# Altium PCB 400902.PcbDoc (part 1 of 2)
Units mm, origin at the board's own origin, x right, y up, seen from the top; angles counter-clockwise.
Board outline 45.72 x 50.8 mm, 4 copper layers (Top Layer, Mid-Layer 1, Mid-Layer 2, Bottom Layer), stack 1.564 mm thick; 61 components, 50 nets, 204 pads, 509 vias.
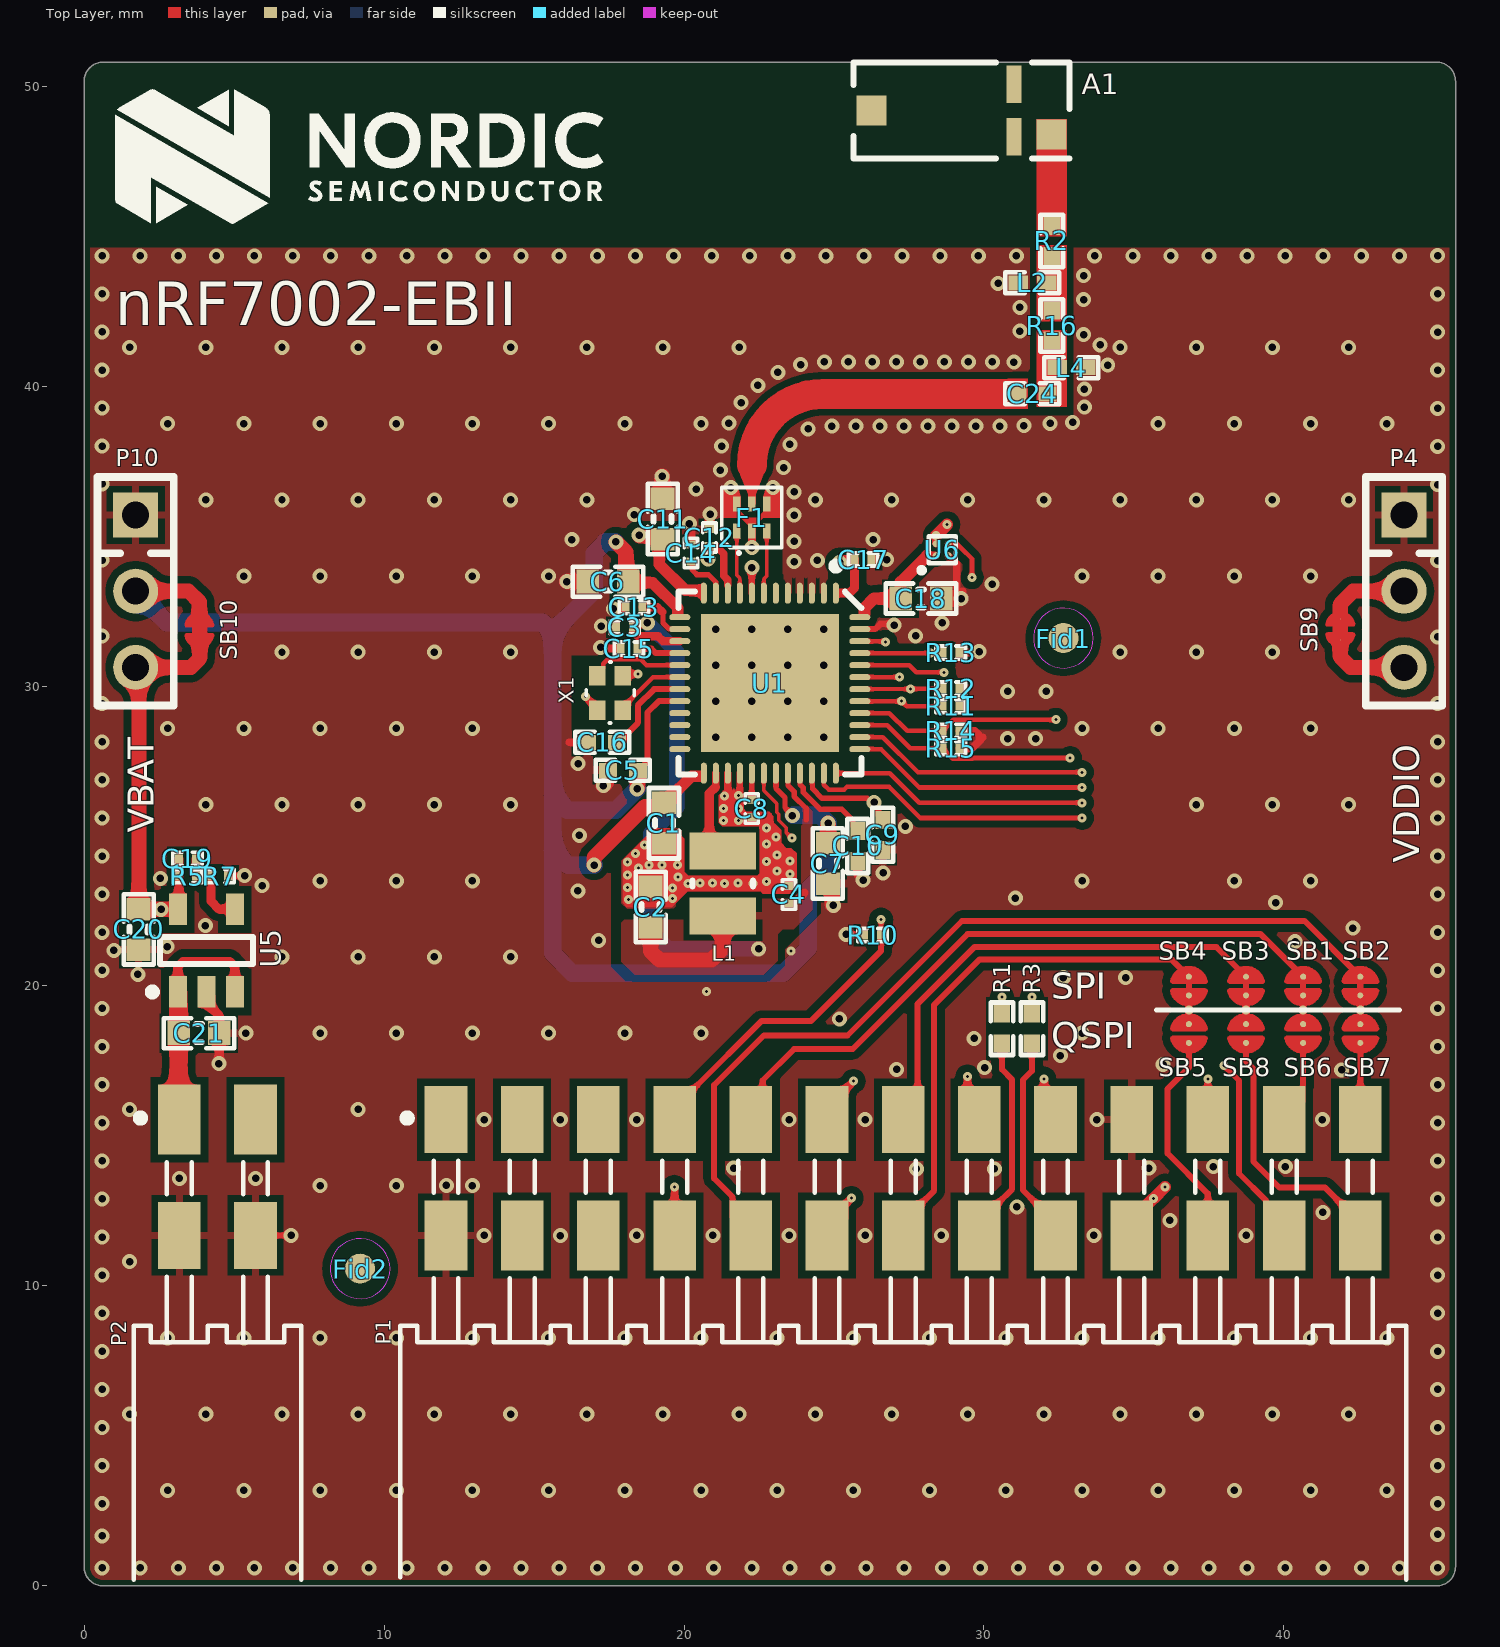
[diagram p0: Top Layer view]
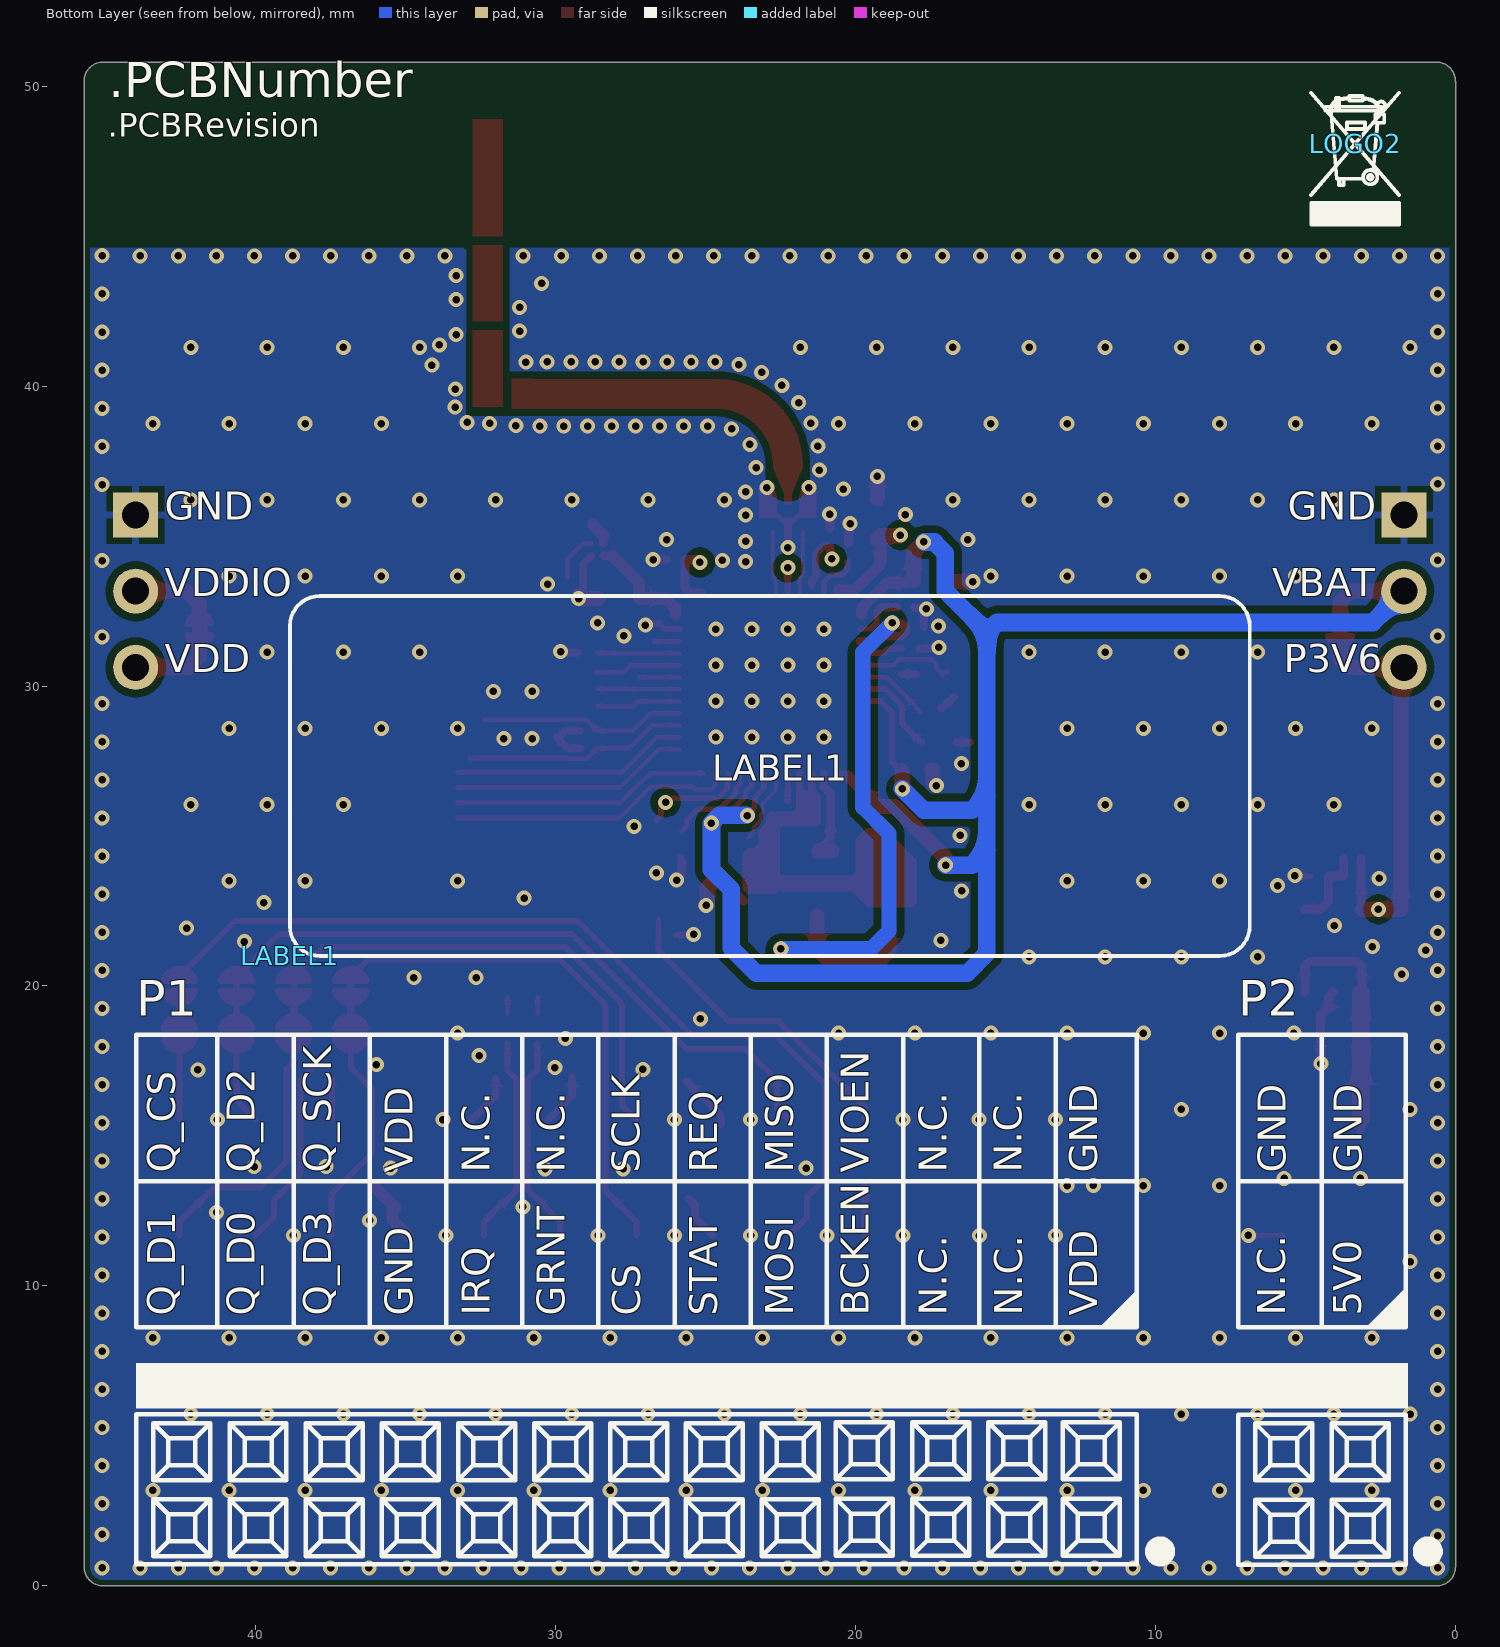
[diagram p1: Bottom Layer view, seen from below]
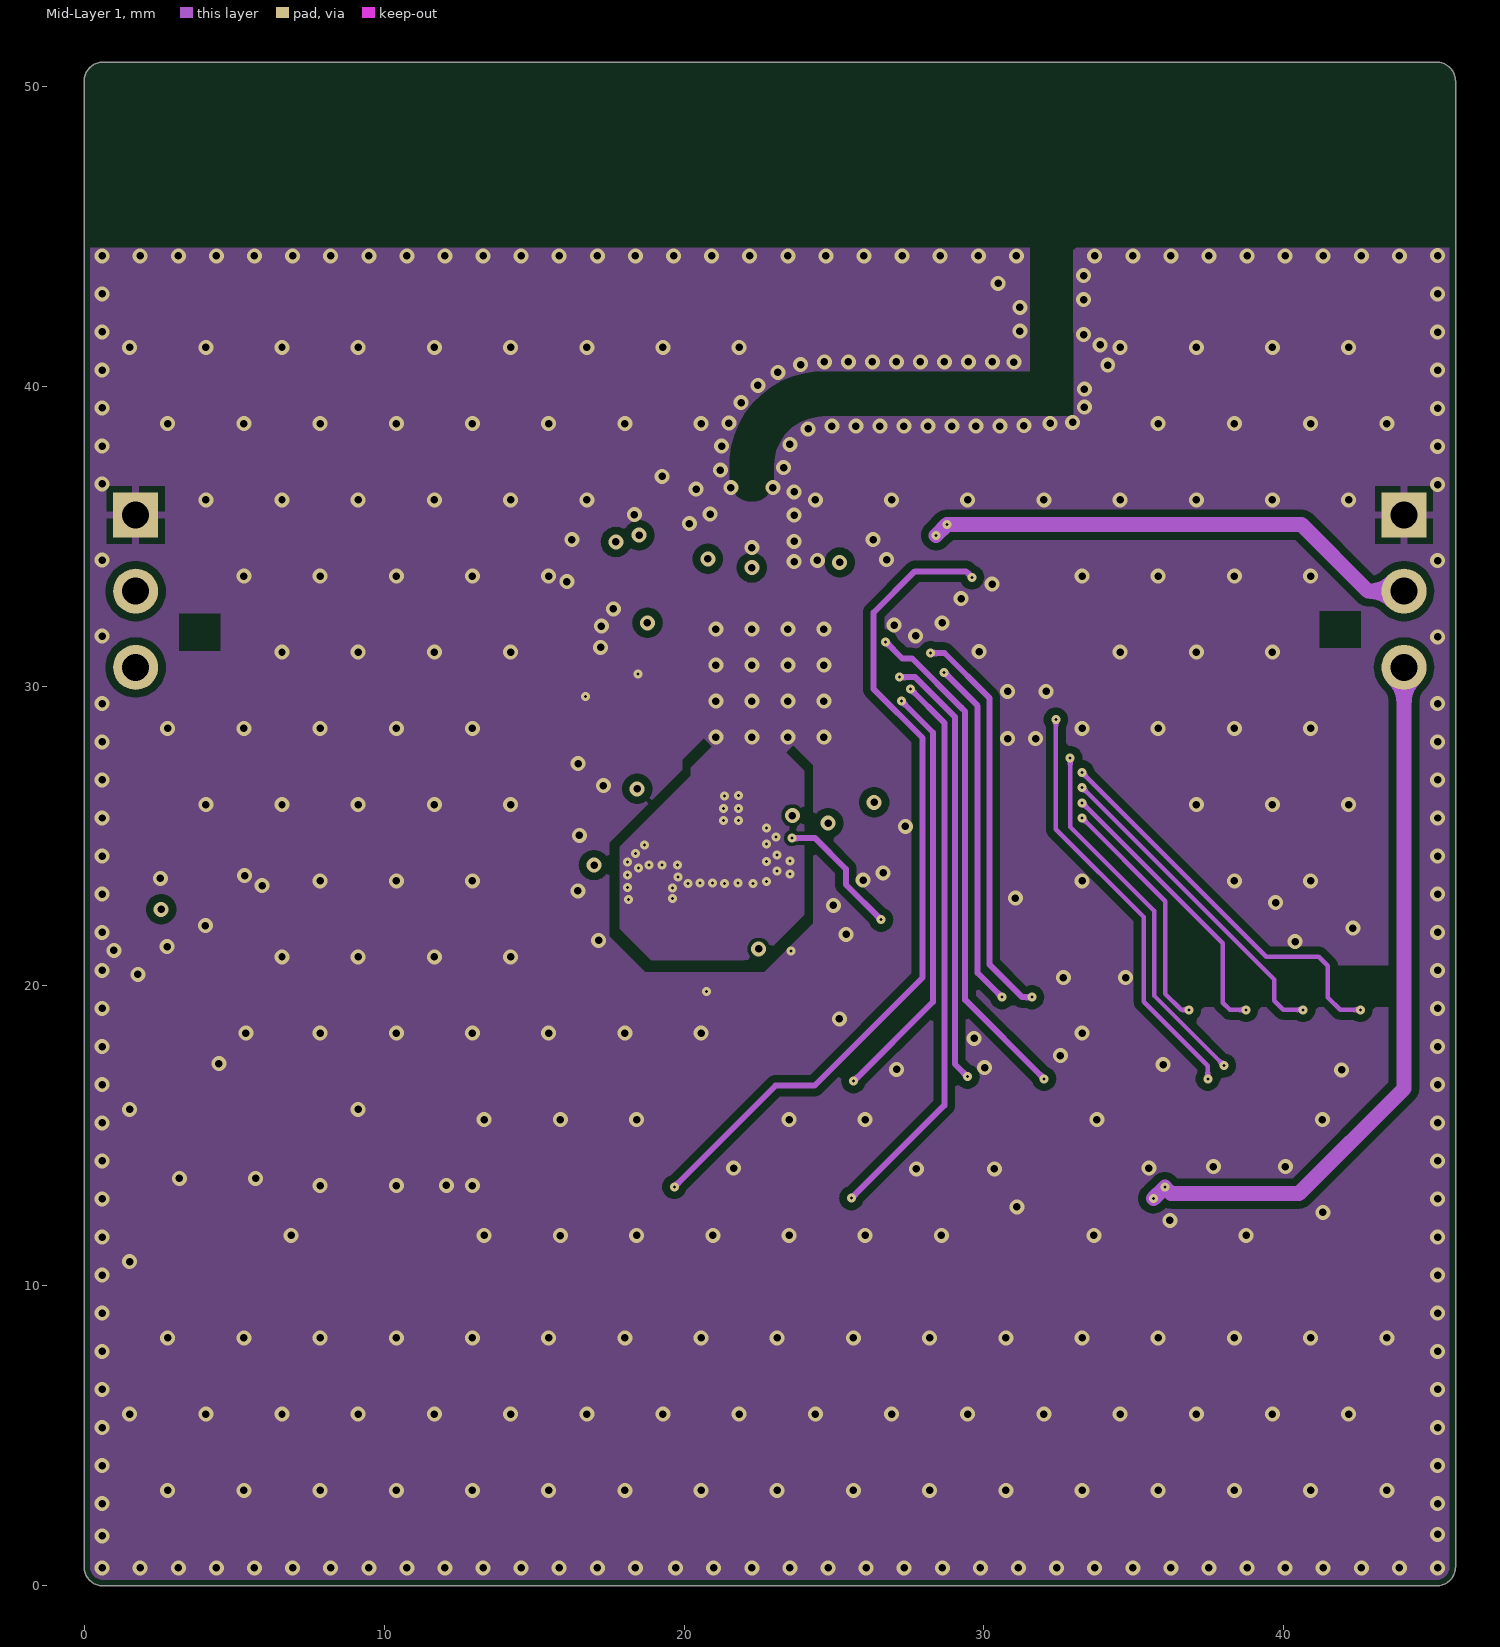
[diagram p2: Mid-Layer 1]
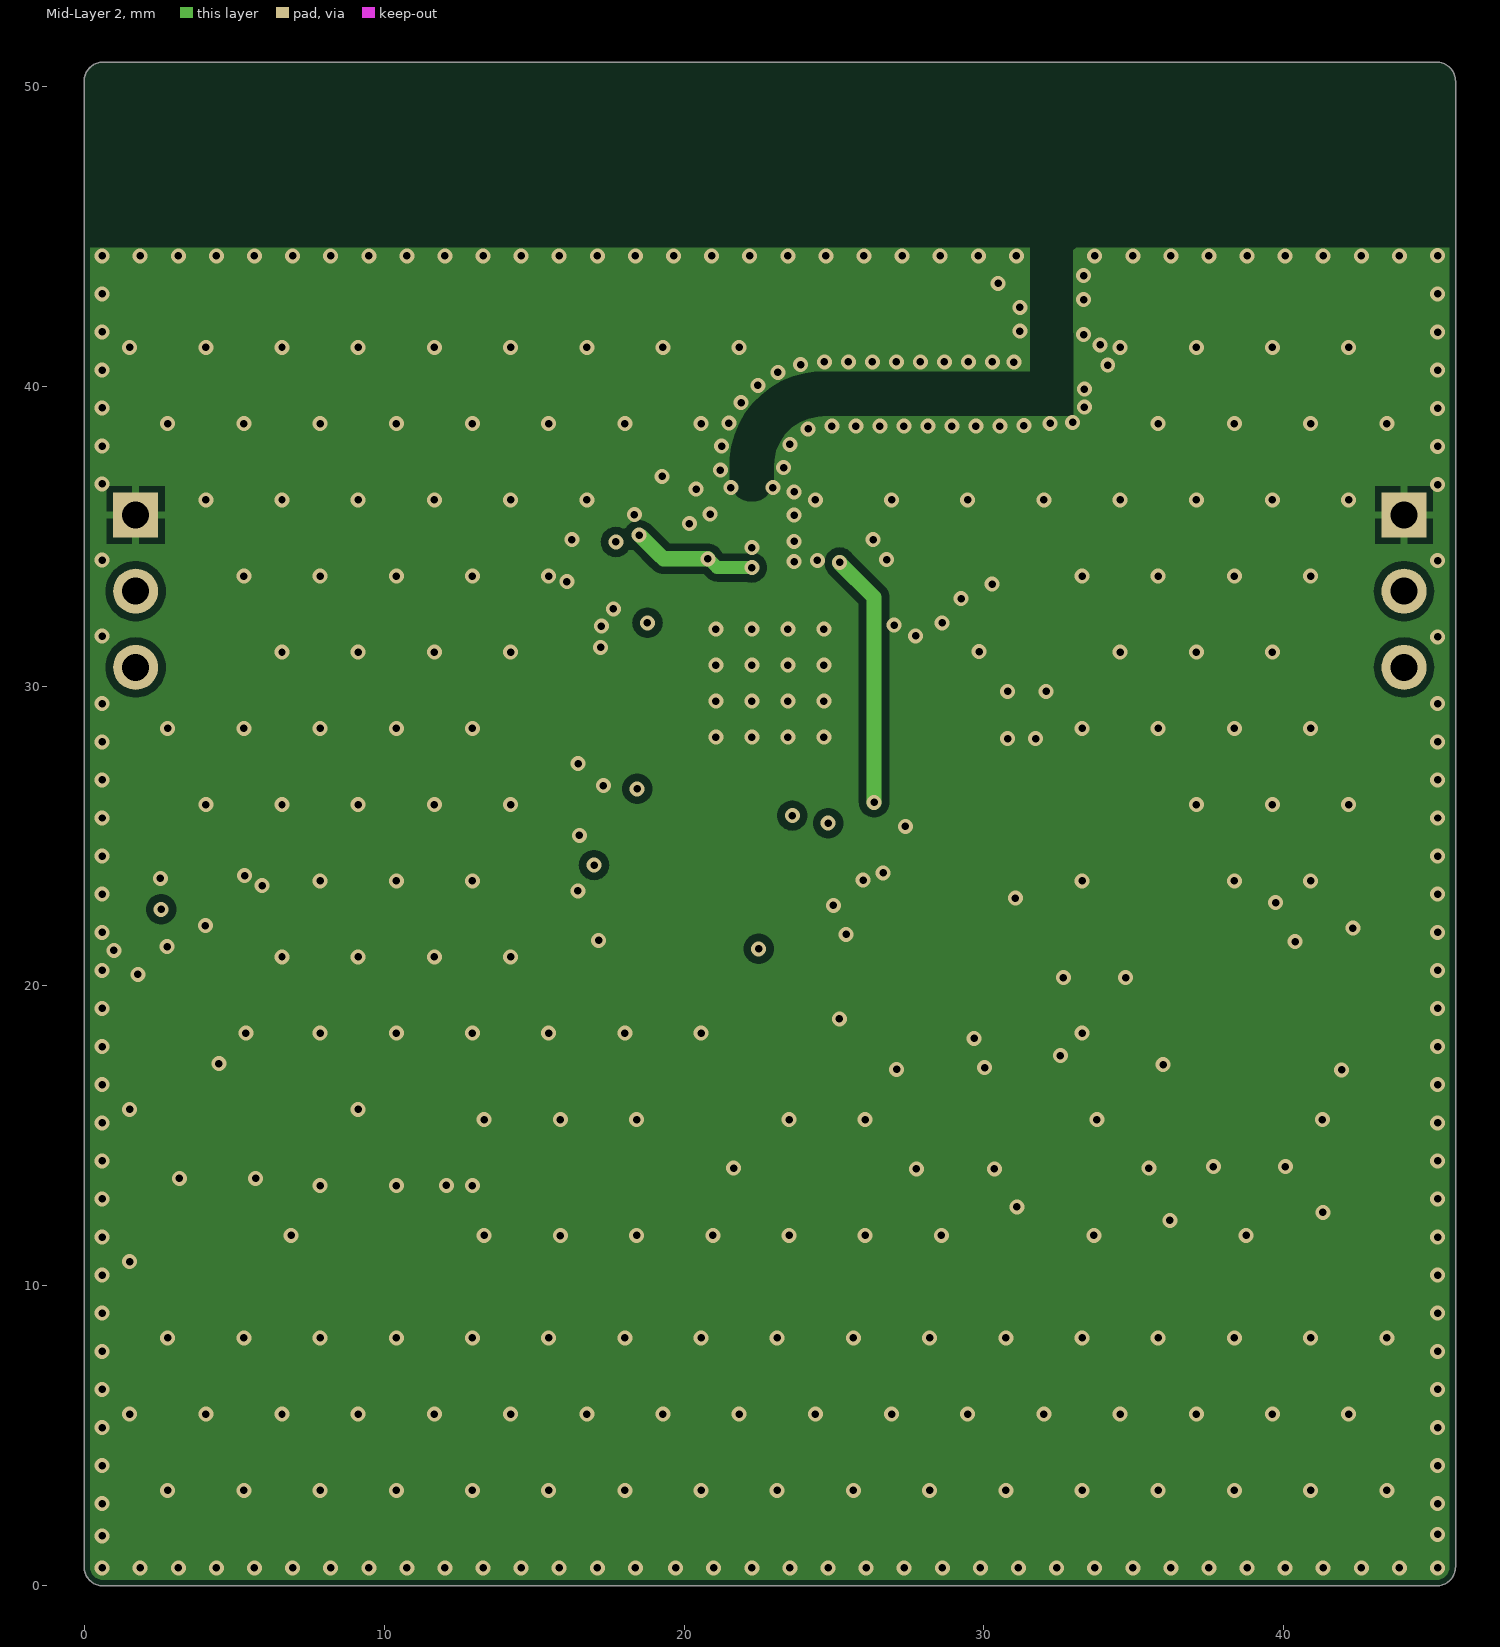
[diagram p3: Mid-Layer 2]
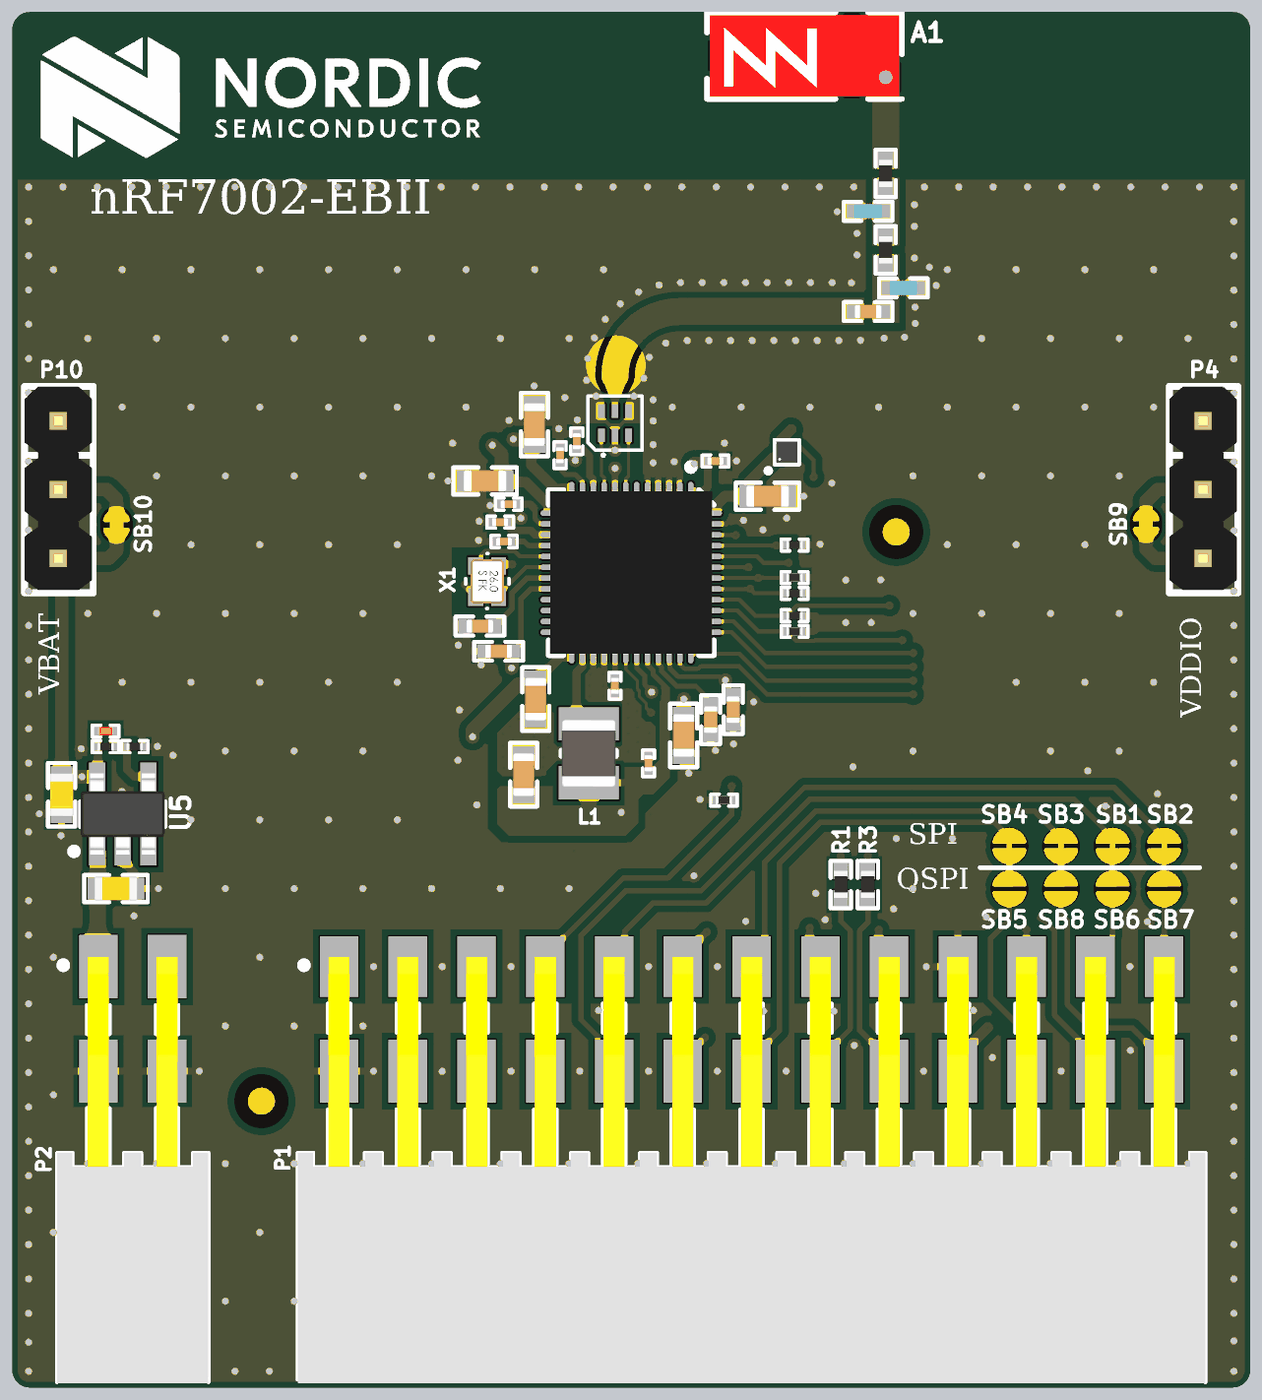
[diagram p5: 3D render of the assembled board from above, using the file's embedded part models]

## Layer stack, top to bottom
Top Solder: solder mask 0.0254, Solder Resist Blue, Dk 4
Top Layer: signal copper 0.0356
Dielectric1: prepreg 0.076, FR-4, Dk 4.4
Mid-Layer 1: signal copper 0.0356
Dielectric2: core 1.27, FR-4, Dk 4.4
Mid-Layer 2: signal copper 0.0356
Dielectric3: prepreg 0.076, FR-4, Dk 4.4
Bottom Layer: signal copper 0.0356
Bottom Solder: solder mask 0.0254, Solder Resist Blue, Dk 4

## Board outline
0,0.635 ccw(c0.635,0.635) 0.635,0 45.085,0 ccw(c45.085,0.635) 45.72,0.635 45.72,50.164 ccw(c45.085,50.164) 45.085,50.799 45.085,50.8 0.636,50.8 0.636,50.799 ccw(c0.636,50.164) 0.001,50.164 0,50.164

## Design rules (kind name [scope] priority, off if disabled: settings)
BoardOutlineClearance [Not (InComponent('A1') or InComponent('P1')or InComponent('P2') or HasPad('Free-666'))] p1: gap=0.2 ignorepadtopadclearanceinfootprint=FALSE
Clearance RF_Clerance [InNetClass('RF') vs InPoly] p1: gap=0.23 ignorepadtopadclearanceinfootprint=FALSE
Clearance Polygon_Clearance [(InNamedPolygon('Top_Layer-GND')) or (InNamedPolygon('Bottom_Layer-GND')) or (InNamedPolygon('Mid_Layer_1-GND')) or (InNamedPolygon('Mid_Layer_2-GND'))] p2: gap=0.25 ignorepadtopadclearanceinfootprint=FALSE
Clearance U1_Clearance [TouchesRoom('nRF7002_room') vs OnTopLayer] p3: gap=0.12 ignorepadtopadclearanceinfootprint=FALSE
Clearance [All] p4: gap=0.125 ignorepadtopadclearanceinfootprint=FALSE
DiffPairsRouting [All] p1: maxlimit=0.254 minlimit=0.15 mostfreqgap=0.254 toplayer_maxgap=0.15 toplayer_prefgap=0.15 toplayer_minwidth=0.203 toplayer_maxwidth=0.381 toplayer_prefwidth=0.381 midlayer1_mingap=0.254 midlayer1_minwidth=0.203 midlayer1_maxwidth=0.381 midlayer1_prefwidth=0.381 midlayer2_mingap=0.254 midlayer2_minwidth=0.203 midlayer2_maxwidth=0.381 midlayer2_prefwidth=0.381 bottomlayer_maxgap=0.15 bottomlayer_prefgap=0.15 bottomlayer_minwidth=0.203 bottomlayer_maxwidth=0.381 bottomlayer_prefwidth=0.381 maxuncoupledlength=12.7
FabricationTestPointUsage TestPointUsage [All] p1: valid=0 allowmultiple=FALSE
FabricationTestpoint Testpoint [All] p1: side=3 testpointundercomponent=TRUE minsize=1.016 maxsize=2.54 preferedsize=1.524 minholesize=0 maxholesize=1.016 preferedholesize=0.813 testpointgrid=0.025 allowsidetop=TRUE allowsidebottom=TRUE usegrid=TRUE gridtolerance=0
Height [All] p1 off: minheight=0 maxheight=25.4 prefheight=12.7
HoleSize [All] p1: absolutevalues=TRUE maxlimit=5 minlimit=0.1 maxpercent=80.000 minpercent=20.000
HoleToHoleClearance [All] p1: gap=0.25 allowstackedmicrovias=FALSE
MinimumAnnularRing [All] p1: minimumring=0.1
MinimumSolderMaskSliver [Not InComponent('U1')] p1: minsoldermaskwidth=0.075
PolygonConnect PolygonConnect_Via [isVia and innet(gnd)] p1: connectstyle=Direct reliefconductorwidth=0.254 reliefentries=4 polygonreliefangle="90 Angle" airgapwidth=0.254
PolygonConnect PolygonConnect_footprint [HasFootprint('INDC1005X04L_C2') or  HasFootprint('CAPC1005X04L_C2') or  HasFootprint('RESC1005X04L_C2') or   HasFootprint('CAPC1608X06L') or  HasFootprint('CAPC2012X11L') or  HasFootprint('SOT95P280X140-5N')] p2: connectstyle=Direct reliefconductorwidth=0.254 reliefentries=4 polygonreliefangle="90 Angle" airgapwidth=0.254
PolygonConnect [All] p3: connectstyle=Relief reliefconductorwidth=0.254 reliefentries=4 polygonreliefangle="90 Angle" airgapwidth=0.213
RoomDefinition nRF7002_room [False vs False] p1: confinementstyle=ConfineIn formatcopy=TRUE lockcomponents=FALSE outline 15.374,37.727 29.243,37.727 29.243,25.1 15.374,25.1
RoutingVias [All] p1: holewidth=0.25 width=0.5 viastyle="Through Hole" minholewidth=0.1 minwidth=0.5 maxholewidth=0.711 maxwidth=1.27
SilkToSolderMaskClearance SilkscreenOverComponentPads [IsPad vs Not (HasFootprint('CAPC1608X06L') or HasFootprint('CAPC0603X03L_C') or HasFootprint('CAPC1005X04L') or HasFootprint('INDC1005X04L') or HasFootprint('RESC0603X03L_C') or HasFootprint('LED_0603_G') or HasFootprint('BGA4C40P2X2_76X76X62') or  HasFootprint('RESC1005X04L') or HasFootprint('INDC1005X04L_WW'))] p1: minsilkscreentomaskgap=0.1 clearancetoexposedcopper=TRUE
SolderMaskExpansion SolderMaskExpansion_via [IsVia] p1: expansion=0.076 istentingtop=TRUE
SolderMaskExpansion SolderMaskExpansion_1 [All] p2: expansion=0.076 istentingtop=FALSE
Width U1_Width [All] p1: maxlimit=2.54 minlimit=0.11 preferedwidth=0.15
Width [All] p2: maxlimit=2.54 minlimit=0.15 preferedwidth=0.15
22 further rules are at their usual default settings.

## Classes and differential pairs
net class RF: ANT ANTWIFI NetC24_1 NetL2_2 TXRF0 TXRF1

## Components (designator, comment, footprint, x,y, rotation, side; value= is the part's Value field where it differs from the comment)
A1 "NN03-320" NN03-320 29.257,49.19 r0 top locked
C1 "4.7µF" CAPC1608X06L 19.332,25.426 r90 top
C2 "4.7µF" CAPC1608X06L 18.887,22.632 r270 top
C3 "0.22µF" CAPC0603X03L_C 18.018,31.959 r0 top
C4 "0.47µF" CAPC0603X03L_C 23.499,23.052 r270 top
C5 "1.0µF" CAPC1005X04L 17.962,27.191 r0 top
C6 "4.7µF" CAPC1608X06L 17.461,33.481 r0 top
C7 "2.2µF" CAPC1608X06L 24.796,24.083 r270 top
C8 "10nF" CAPC0603X03L_C 22.258,25.916 r270 top
C9 "2.2µF" CAPC1005X04L 26.63,25.037 r90 top
C10 "1.0µF" CAPC1005X04L 25.794,24.667 r270 top
C11 "4.7µF" CAPC1608X06L 19.285,35.563 r270 top
C12 "100nF" CAPC0603X03L_C 20.848,34.947 r90 top
C13 "22nF" CAPC0603X03L_C 18.331,32.626 r0 top
C14 "0.47µF" CAPC0603X03L_C 20.232,34.432 r270 top
C15 "2.2µF" CAPC0603X03L_C 18.162,31.245 r0 top
C16 "1.0µF" CAPC1005X04L 17.27,28.121 r0 top
C17 "100nF" CAPC0603X03L_C 25.971,34.217 r180 top
C18 "2.2µF" CAPC1608X06L 27.898,32.917 r180 top
C19 "82pF" CAPC0603X03L_C 3.443,24.24 r0 top locked
C20 "4.7µF" CAPC1608X06L 1.818,21.89 r90 top locked
C21 "4.7µF" CAPC1608X06L 3.825,18.425 r180 top locked
C24 "0.7pF" CAPC1005X04L 31.61,39.738 r180 top
F1 "LFD_Diplexer" CAF-50P160X80-6N 22.26,35.615 r90 top value=LFD182G45DCJD247
Fid1 "Fiducial mark" Fiducial 32.647,31.597 r0 top value=N.A.
Fid2 "Fiducial mark" Fiducial 9.2,10.575 r0 top value=N.A.
L1 "3.3µH" INDC2520X10N 21.289,23.421 r270 top
L2 "7.0nH" INDC1005X04L_WW 31.61,43.441 r0 top locked
L4 "2.4nH" INDC1005X04L_WW 32.91,40.612 r180 top
LABEL1 "12x32mm" LabelSilk_12x32 38.86,21 r180 bottom
LOGO2 "WEE Symbol" WEEE_3x4.5mm 3.35,48.075 r180 bottom
P1 "Socket 2x13, Angled" SOCKET_ANG_2x13_SMD-2.54mm-Mirrored 27.305,13.614 r0 top locked
P2 "Socket 2x2, Angled" SOCKET_ANG_2x2_SMD-2.54mm-Mirrored 4.445,13.614 r0 top locked
P4 "Pin List 1x3" LIST_1x3 44.003,33.16 r270 top
P10 "Pin List 1x3" LIST_1x3 1.718,33.16 r270 top
R1 "0R" RESC1005X04L 30.6,18.575 r90 top
R2 "0R" RESC1005X04L 32.26,44.84 r270 top locked
R3 "0R" RESC1005X04L 31.6,18.575 r90 top
R5 "560k" RESC0603X03L_C 3.443,23.665 r180 top locked
R7 "160k" RESC0603X03L_C 4.518,23.665 r180 top locked
R10 "100k" RESC0603X03L_C 26.286,21.694 r180 top
R11 "100k" RESC0603X03L_C 28.894,29.332 r0 top
R12 "100k" RESC0603X03L_C 28.894,29.91 r0 top
R13 "100k" RESC0603X03L_C 28.894,31.114 r180 top
R14 "100k" RESC0603X03L_C 28.894,28.503 r0 top
R15 "100k" RESC0603X03L_C 28.894,27.925 r0 top
R16 "0R" RESC1005X04L 32.26,42.015 r270 top locked
SB1 "Solderbridge" Solderbridge_SHORTED_0.4 40.64,19.997 r90 top locked net-tie
SB2 "Solderbridge" Solderbridge_SHORTED_0.4 42.545,19.997 r90 top locked net-tie
SB3 "Solderbridge" Solderbridge_SHORTED_0.4 38.735,19.997 r90 top locked net-tie
SB4 "Solderbridge" Solderbridge_SHORTED_0.4 36.83,19.997 r90 top locked net-tie
SB5 "Solderbridge" Solderbridge_0.4#1 36.83,18.415 r270 top locked
SB6 "Solderbridge" Solderbridge_0.4#1 40.64,18.415 r270 top locked
SB7 "Solderbridge" Solderbridge_0.4#1 42.545,18.415 r270 top locked
SB8 "Solderbridge" Solderbridge_0.4#2 38.735,18.415 r270 top locked
SB9 "Solderbridge" Solderbridge_Shorted_Power 41.872,31.883 r270 top net-tie
SB10 "Solderbridge" Solderbridge_Shorted_Power 3.85,31.86 r90 top net-tie
U1 "nRF7002-QFAA" QFN40P600X600X60-48N 22.86,30.095 r270 top
U5 "AP2127" SOT95P282X145-5N 4.075,21.175 r90 top locked
U6 "TCK106AG" BGA4C40P2X2_76X76X62 28.608,34.544 r90 top
X1 "40MHz" BT-XTAL_1612 17.539,29.771 r270 top locked

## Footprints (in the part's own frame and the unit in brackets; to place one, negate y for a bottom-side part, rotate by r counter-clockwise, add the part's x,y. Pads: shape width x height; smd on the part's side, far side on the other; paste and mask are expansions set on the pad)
BGA4C40P2X2_76X76X62 [mm] "BGA, 4-Leads, Body 0.8x0.8mm,  Pitch 0.40mm"
  round 0.235 smd mask+0.04: A1(-0.2,0.2) A2(0.2,0.2) B1(-0.2,-0.2) B2(0.2,-0.2)
  silkscreen extent -0.74,-0.45 0.45,0.74, body extent -0.39,-0.39 0.4,0.4, height 0.55
BT-XTAL_1612 [mm] "Crystal 1.6 x 1.2 mm"
  rect 0.65x0.55 smd: 1(-0.575,-0.425) 2(0.575,-0.425) 3(0.575,0.425) 4(-0.575,0.425)
  silkscreen extent -1.03,-0.8 1,0.8, body extent -0.83,-0.63 0.83,0.63, height 0.41
CAF-50P160X80-6N [mm] "Chip Array, Flat, 6-Leads, Pitch 0,50mm,  Body 1,60x0,80mm,  IPC Medium Density"
  rect 0.5x0.25 smd mask+0.08: 1(-0.45,0.5) 2(-0.45,0) 3(-0.45,-0.5) 5(0.45,-0.5) 6(0.45,0) 7(0.45,0.5)
  Top Layer region: 0.7,0.375 0.2,0.375 0,0.175 0,-0.175 0.2,-0.375 0.7,-0.375 0.966,-0.462 1,-0.95 0,-0.95 0,-0.375 -0.25,-0.125 -0.8,-0.125 -0.9,-0.225 -1,-0.225 -1,0.225 -0.9,0.225 -0.8,0.125 -0.25,0.125 0,0.375 0,0.95 1,0.95 0.966,0.457
  silkscreen extent -1.23,-1 1,1, body extent -0.5,-0.88 0.5,0.88, height 0.67
CAPC0603X03L_C [mm] "Chip Capacitor, 2-Leads, Body 0.6x0.3mm, IPC High Density"
  rect 0.27x0.3 smd mask+0.05: 1(-0.285,0) 2(0.285,0)
  silkscreen extent -0.49,-0.22 0.49,0.22, body extent -0.3,-0.15 0.3,0.15, height 0.3
CAPC1005X04L [mm] "Chip Capacitor, 2-Leads, Body 1.0x0.5mm, IPC High Density"
  rect 0.6x0.5 smd: 1(-0.5,0) 2(0.5,0)
  silkscreen extent -0.9,-0.35 0.9,0.35, body extent -0.5,-0.25 0.5,0.25, height 0.5
CAPC1608X06L [mm] "Chip Capacitor, 2-Leads, Body 1.6x0.8mm, IPC High Density"
  rect 0.75x0.8 smd: 1(-0.675,0) 2(0.675,0)
  silkscreen extent -1.17,-0.5 1.17,0.5, body extent -0.8,-0.4 0.8,0.4, height 0.8
Fiducial [mm] "Fiducial Mark"
  round 1 smd paste-2539.97 mask+0.5: 0(0,0)
  Top Layer keep-out circle w0.01: c0,0 r1
INDC1005X04L_WW [mm] "Chip Inductor, 2-Leads, Body 1.0x0.5mm, IPC High Density"
  rect 0.65x0.5 smd: 1(-0.475,0) 2(0.475,0)
  silkscreen extent -0.9,-0.35 0.9,0.35, body extent -0.5,-0.3 0.5,0.3, height 0.51
INDC2520X10N [mm] "Chip Inductor, 2-Leads, Body 2,50x2,00mm, IPC Medium Density"
  rect 1.23x2.22 smd: 1(-1.085,0) 2(1.085,0)
  silkscreen extent -0.1,-1.01 0.1,1.01, body extent -1.25,-1 1.25,1, height 1.2
LabelSilk_12x32 [mm] "PCA version label, stick-on, 12x32mm"
  silkscreen extent 0,0 32,12, body extent 0,0 32,12, height 0.05
LIST_1x3 [mm] "Pin List, 2.54mm through hole"
  rect 1.5x1.5 hole 0.9: 1(-2.54,0)
  round 1.5 hole 0.9: 2(0,0) 3(2.54,0)
  silkscreen extent -3.81,-1.27 3.81,1.27, body extent -3.81,-1.27 3.71,1.23, height 8.2
NN03-320 [mm]
  rect 1x1 smd: 1(-3,0) 4(3,-0.8)
  rect 0.5x1.25 smd: 2(1.75,-0.875) 3(1.75,0.875)
  Multi-Layer pour cut-out: -3.5,1.5 3.5,1.5 3.5,-1.5 -3.5,-1.5
  silkscreen extent -3.6,-1.6 3.6,1.6, body extent -3.5,-1.5 3.5,1.5, height 2.01
QFN40P600X600X60-48N [mm] "QFN, 48-Leads, Body 6.1x6.1mm (max), Pitch 0.40mm, IPC Medium Density"
  oval 0.7x0.2 smd: 1(-3,2.2) 2(-3,1.8) 3(-3,1.4) 4(-3,1) 5(-3,0.6) 6(-3,0.2) 7(-3,-0.2) 8(-3,-0.6) 9(-3,-1) 10(-3,-1.4) 11(-3,-1.8) 12(-3,-2.2) 25(3,-2.2) 26(3,-1.8) 27(3,-1.4) 28(3,-1) 29(3,-0.6) 30(3,-0.2) 31(3,0.2) 32(3,0.6) 33(3,1) 34(3,1.4) 35(3,1.8) 36(3,2.2)
  oval 0.2x0.7 smd: 13(-2.2,-3) 14(-1.8,-3) 15(-1.4,-3) 16(-1,-3) 17(-0.6,-3) 18(-0.2,-3) 19(0.2,-3) 20(0.6,-3) 21(1,-3) 22(1.4,-3) 23(1.8,-3) 24(2.2,-3) 37(2.2,3) 38(1.8,3) 39(1.4,3) 40(1,3) 41(0.6,3) 42(0.2,3) 43(-0.2,3) 44(-0.6,3) 45(-1,3) 46(-1.4,3) 47(-1.8,3) 48(-2.2,3)
  rect 4.6x4.6 smd: 49(0,0)
  silkscreen extent -4.02,-3.05 3.05,3.05, body extent -3.02,-3.02 3.02,3.02, height 0.86
RESC0603X03L_C [mm] "Chip Resistor, 2-Leads, Body 0.6x0.3mm, IPC High Density"
  rect 0.27x0.3 smd: 1(-0.285,0) 2(0.285,0)
  silkscreen extent -0.49,-0.22 0.49,0.22, body extent -0.3,-0.15 0.3,0.15, height 0.23
RESC1005X04L [mm] "Chip Resistor, 2-Leads, Body 1.0x0.5mm, IPC High Density"
  rect 0.6x0.55 smd mask+0.05: 1(-0.5,0) 2(0.5,0)
  silkscreen extent -0.88,-0.38 0.88,0.38, body extent -0.5,-0.25 0.5,0.25, height 0.3
SOCKET_ANG_2x2_SMD-2.54mm-Mirrored [mm]
  rect 1.42x2.34 smd mask+0.05: 1(-1.27,1.93) 3(1.27,1.93)
  rect 1.42x2.24 smd mask+0.05: 2(-1.27,-1.931) 4(1.27,-1.93)
  silkscreen extent -2.8,-13.41 2.8,2.11, body extent -2.79,-13.46 2.79,2.29, height 4.96
SOCKET_ANG_2x13_SMD-2.54mm-Mirrored [mm] "2.54mm pitch, Female, Socket, 2-rows, 26 positions. / Mirrored pin 1 numbering."
  rect 1.42x2.24 smd mask+0.05: 1(-15.24,1.93) 3(-12.7,1.93) 5(-10.16,1.93) 7(-7.62,1.93) 9(-5.08,1.93) 11(-2.54,1.93) 13(0,1.93) 15(2.54,1.93) 17(5.08,1.93) 19(7.62,1.93) 21(10.16,1.931) 23(12.7,1.931) 25(15.24,1.93)
  rect 1.42x2.34 smd mask+0.05: 2(-15.24,-1.93) 4(-12.7,-1.93) 6(-10.16,-1.93) 8(-7.62,-1.93) 10(-5.08,-1.93) 12(-2.54,-1.93) 14(0,-1.93) 16(2.54,-1.93) 18(5.08,-1.93) 20(7.62,-1.93) 22(10.16,-1.93) 24(12.7,-1.93) 26(15.24,-1.93)
  silkscreen extent -16.76,-13.41 16.76,2.11, body extent -16.76,-13.46 16.76,2.29, height 5.02
Solderbridge_0.4#1 [mm]
  round 0.2 smd paste-10: 1(-0.312,0) 2(0.312,0)
  Top Layer region: -0.077,-0.553 -0.129,-0.605 -0.205,-0.554 -0.409,-0.351 -0.462,-0.292 -0.521,-0.193 -0.549,-0.099 -0.544,0.122 -0.518,0.193 -0.434,0.33 -0.351,0.411 -0.259,0.469 -0.159,0.556 -0.08,0.565
  Top Layer region: 0.077,0.553 0.203,0.512 0.335,0.424 0.409,0.351 0.462,0.292 0.521,0.193 0.549,0.099 0.544,-0.122 0.518,-0.193 0.434,-0.33 0.351,-0.411 0.152,-0.536 0.077,-0.559
  Top Layer lines w0.152: -0.153,-0.558 cw(c-0.035,0) -0.605,0 cw(c-0.035,0) -0.156,0.557 ; 0.153,-0.557 ccw(c0.03,0) 0.153,0.557
Solderbridge_0.4#2 [mm]
  round 0.2 smd paste-10: 1(-0.312,0) 2(0.312,0)
  Top Layer region: -0.077,-0.553 -0.129,-0.605 -0.205,-0.554 -0.409,-0.351 -0.462,-0.292 -0.521,-0.193 -0.549,-0.099 -0.544,0.122 -0.518,0.193 -0.434,0.33 -0.351,0.411 -0.259,0.469 -0.159,0.556 -0.08,0.565
  Top Layer region: 0.077,0.553 0.203,0.512 0.335,0.424 0.409,0.351 0.462,0.292 0.521,0.193 0.549,0.099 0.544,-0.122 0.518,-0.193 0.434,-0.33 0.351,-0.411 0.152,-0.536 0.077,-0.559
  Top Layer lines w0.152: -0.153,-0.558 cw(c-0.035,0) -0.605,0 cw(c-0.035,0) -0.156,0.557 ; 0.153,-0.557 ccw(c0.03,0) 0.6,0 ccw(c0.03,0) 0.153,0.557
Solderbridge_SHORTED_0.4 [mm]
  round 0.2 smd paste-10: 1(-0.312,0) 2(0.312,0)
  Top Layer region: 0.077,0.553 0.203,0.512 0.335,0.424 0.409,0.351 0.462,0.292 0.521,0.193 0.549,0.099 0.544,-0.122 0.518,-0.193 0.434,-0.33 0.351,-0.411 0.152,-0.536 0.077,-0.559
  Top Layer region: -0.077,-0.553 -0.129,-0.605 -0.205,-0.554 -0.409,-0.351 -0.462,-0.292 -0.521,-0.193 -0.549,-0.099 -0.544,0.122 -0.518,0.193 -0.434,0.33 -0.351,0.411 -0.259,0.469 -0.159,0.556 -0.08,0.565
  Top Layer lines w0.152: -0.156,0.557 ccw(c-0.035,0) -0.153,-0.558 ; 0.153,0.557 cw(c0.03,0) 0.153,-0.557
  Top Layer lines w0.203: -0.312,0 0.363,0
Solderbridge_Shorted_Power [mil]
  round 1 smd paste-99999: 1(-13.84,0.21) 2(13.72,0.21)
  Top Layer region: -4.92,9.84 4.92,9.84 4.92,-9.84 -4.92,-9.84
  Top Layer region: 7.43,-19.16 15.71,-15.53 21.49,-8.59 23.56,0.21 23.56,0.21 21.49,9 15.71,15.94 7.43,19.57 7.43,19.57 6.12,19.52 4.96,18.92 4.16,17.89 3.88,16.61 3.88,16.61 3.88,-16.2 4.16,-17.47 4.96,-18.51 6.12,-19.11 7.43,-19.16
  Top Layer region: -7.54,19.57 -15.82,15.94 -21.61,9 -23.68,0.21 -23.68,0.21 -21.61,-8.59 -15.82,-15.53 -7.54,-19.16 -7.54,-19.16 -6.24,-19.11 -5.08,-18.51 -4.28,-17.47 -3.99,-16.2 -3.99,-16.2 -3.99,16.61 -4.28,17.89 -5.08,18.92 -6.24,19.52 -7.54,19.57
SOT95P282X145-5N [mm] "SOT23, 5-Leads, Body 2.96x2.82mm, Pitch 0.95mm, IPC Medium Density"
  rect 1.05x0.6 smd: 1(-1.375,0.95) 2(-1.375,0) 3(-1.375,-0.95) 4(1.375,-0.95) 5(1.375,0.95)
  silkscreen extent -1.5,-1.55 0.45,1.92, body extent -1.5,-1.55 1.5,1.55, height 1.45
WEEE_3x4.5mm [mm]
  silkscreen extent -1.47,-2.7 1.47,1.71

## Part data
A1: "Dual-Band GNSS and Wi-Fi/BluetoothAntenna", Manufacturer=Ignion, Part number IPS=N.A., Part number NEMS=100700066, Supplier Part Number 1=2115-NN03-320CT-ND
C1 C2 C6 C11: library part C0603-4µ7-25V-X6S-GRM188C81E475KE11, "Capacitor, Ceramic, 4.7µF 25V X6S 0603,±10%", Manufacturer=Murata, Manufacturer Part Number=GRM188C81E475KE11D, Part number IPS=N.A., Part number NEMS=100200486, Supplier Part Number 1=490-7199-1-ND
C3: library part C0201-220n-10V-X5R-GRM033R61A224KE90, "Capacitor, Ceramic, 0.22µF 10V X5R 0201, ±10%", Manufacturer=Murata, Manufacturer Part Number=GRM033R61A224KE90D, Part number IPS=N.A., Part number NEMS=100200487, Supplier Part Number 1=81-GRM33R61A224KE90D
C4 C14: library part C0201-470n-6.3V-X5R-GRM033R60J474KE90, "Capacitor, Ceramic, 0.47µF 6.3V X5R 0201,±10%", Manufacturer=Murata, Manufacturer Part Number=GRM033R60J474KE90D, Part number IPS=N.A., Part number NEMS=100200488, Supplier Part Number 1=490-10409-1-ND
C5: library part C0402-1µ0-35V-X5R-GRM155R6YA105KE11, "Capacitor, Ceramic, 1.0µF 35V X5R 0402,±10%", Manufacturer=Murata, Manufacturer Part Number=GRM155R6YA105KE11D, Part number IPS=N.A., Part number NEMS=100200489, Supplier Part Number 1=81-GRM155R6YA105KE1D
C7 C18: library part C0603-2µ2-16V-X7S-GRM188C71C225KE11, "Capacitor, Ceramic, 2.2µF 16V X7S 0603,±10%", Manufacturer=Murata, Manufacturer Part Number=GRM188C71C225KE11D, Part number IPS=N.A., Part number NEMS=100200490, Supplier Part Number 1=81-GRM188C71C225KE1D
C8: library part C0201-10n-16V-X7R-GRM033R71C103KE14, "Capacitor, Ceramic, 10nF 16V X7R 0201,±10%", Manufacturer=Murata, Manufacturer Part Number=GRM033R71C103KE14D, Part number IPS=N.A., Part number NEMS=100200491, Supplier Part Number 1=490-14453-1-ND
C9: library part C0402-2µ2-25V-X5R-GRM155R61E225KE11, "Capacitor, Ceramic, 2.2µF 25V X5R 0402,±10%", Manufacturer=Murata, Manufacturer Part Number=GRM155R61E225KE11D, Part number IPS=N.A., Part number NEMS=100200492, Supplier Part Number 1=81-GRM155R61E225KE1D
C10: library part C0402-1µ0-16V-X6S-GRM155C81C105KE11D, "Capacitor, Ceramic, 1.0µF 16V X6S 0402,±10%", Manufacturer=Murata, Manufacturer Part Number=GRM155C81C105KE11D, Part number IPS=N.A., Part number NEMS=100200516, Supplier Part Number 1=490-12700-2-ND
C12 C17: library part C0201-100n-16V-X7S-GRM033C71C104KE14, "Capacitor, Ceramic, 100nF 16V X7S 0201,±10%", Manufacturer=Murata, Manufacturer Part Number=GRM033C71C104KE14D, Part number IPS=N.A., Part number NEMS=100200494, Supplier Part Number 1=81-GRM33C71C104KE14D
C13: library part C0201-22n-10V-X5R-GRM033R61A223KE84, "Capacitor, Ceramic, 22nF 10V X5R 0201,±10%", Manufacturer=Murata, Manufacturer Part Number=GRM033R61A223KE84D, Part number IPS=N.A., Part number NEMS=100200495, Supplier Part Number 1=81-GRM033R61A223KE4E
C15: library part C0201-2µ2-10V-X5R-GRM033R61A225KE47, "Capacitor, Ceramic, 2.2µF 10V X5R 0201,±10%", Manufacturer=Murata, Manufacturer Part Number=GRM033R61A225KE47D, Part number IPS=N.A., Part number NEMS=100200496, Supplier Part Number 1=81-GRM033R61A225KE7D
C16: library part C0402-1µ0-10V-X7S-GRM155C71A105KE11, "Capacitor, Ceramic, 1.0µF 10V X7S 0402,±10%", Manufacturer=Murata, Manufacturer Part Number=GRM155C71A105KE11D, Part number IPS=N.A., Part number NEMS=100200497, Supplier Part Number 1=81-GRM155C71A105KE1J
C19: library part C0201-82p, "Chip Cap 0201", Manufacturer=N.A., Part number NEMS=100200043
C20 C21: library part C0603-4.7µ-10V-X7R, "Capacitor, MLCC", Manufacturer=Murata, Manufacturer Part Number=GRM188Z71A475KE15J, Part number IPS=N.A., Part number NEMS=100200438, Supplier Part Number 1=81-GRM188Z71A475KE5J
C24: library part C0402-0.7p-50V-C0G-GJM1555C1HR70WB01, "Capacitor, C0G/NP0, 50V, ±0.05pF, 0402", Manufacturer=Murata, Manufacturer Part Number=GJM1555C1HR70WB01D, Part number IPS=N.A., Part number NEMS=100200707, Supplier Part Number 1=490-11252-1-ND
F1: library part LFD182G45DCJD247, "Signal Conditioning 2.4GHz and 5GHz Diplexer", Manufacturer=Murata, Part number IPS=N.A., Part number NEMS=100800026, Supplier Part Number 1=81-LFD182G45DCJD247
Fid1 Fid2: library part Fid-Mark, "Fiducial Mark", Manufacturer=N.A., Part number NEMS=100500073
L1: library part L1008-3µ3-LQM2HPN3R3MGCL, "Inductor, 1A, ±20%, 200mOhm", Manufacturer=Murata, Manufacturer Part Number=LQM2HPN3R3MGCL, Part number IPS=N.A., Part number NEMS=100300406, Supplier Part Number 1=490-12070-1-ND
L2: library part L0402-7n0-Wirewound-Murata, "Inductor, 570mA, ±2%, 130mΩ", Manufacturer=Murata, Manufacturer Part Number=LQW15AN7N0G00, Part number IPS=N.A., Part number NEMS=100300337
L4: library part L0402-2n4-Wirewound-LQW15AN_80, "Inductor, 2.53A, 2%, 22mΩ, Q=30", Manufacturer=Murata, Manufacturer Part Number=LQW15AN2N4G80, Part number IPS=N.A., Part number NEMS=100300507, Supplier Part Number 1=81-LQW15AN2N4G80D
LABEL1: library part Label_12x32, "PCA version label, stick-on, 12x32mm", Manufacturer="Ellco Etikett", Manufacturer Part Number=68616, Part number IPS=N.A., Part number NEMS=101200029
LOGO2: library part "WEEE Symbol 3x4.5mm", "WEEE Directive symbol", Manufacturer=N.A., Part number NEMS=101100006
P1: library part 2185-213ZG0CYNR3, "Socket 2x13, 2.54mm (100mil), Right Angle, SMD", Manufacturer=WCON, Part number IPS=N.A., Part number NEMS=100500914
P2: library part 2185-202ZS0CYNR3, "Socket 2x2, 2.54mm (100mil), Right Angle, SMD", Manufacturer=WCON, Part number IPS=N.A., Part number NEMS=100500857
P4 P10: "Pin List 1x3, 2.54mm (100mil)", Manufacturer=N.A., Part number NEMS=100500304
R1 R2 R3 R16: library part R0402-0R, "Resistor, ±5%, 0.063W", Manufacturer=N.A., Part number IPS=00000007128, Part number NEMS=100100109, Supplier Part Number 1=146-9661
R5: library part R0201-560k, "Resistor, ±1%, 0.05W", Manufacturer=N.A., Part number IPS=00000004799, Part number NEMS=100100090
R7: library part R0201-160k, "Resistor, ±1%, 0.05W", Manufacturer=N.A., Part number NEMS=100100657
R10 R11 R12 R13 R14 R15: library part R0201-100k, "Resistor, ±1%, 0.05W", Manufacturer=N.A., Part number IPS=00000001419, Part number NEMS=100100080, Part number Norautron=26108487
SB1 SB2 SB3 SB4: library part "Solderbridge Shorted 0.4mm", "Shorted Solderbridge", Manufacturer=N.A., Part number NEMS=100500561
SB5 SB6 SB7 SB8: library part "Solderbridge 0.4mm", Manufacturer=N.A., Part number NEMS=100500560
SB9 SB10: library part "Solderbridge Shorted Power", "Shorted Solderbridge Power", Manufacturer=N.A., Part number NEMS=100500460
U1: library part nRF7002-QFAAB0, "Wi-fi Dual Band Companion chip", Manufacturer="Nordic Semiconductor", Part number IPS=N.A., Part number NEMS=102000276
U5: library part AP2127K-ADJTRG1, "IC REG LDO ADJ 0.3A SOT23-5", Manufacturer="Diodes Incorporated", Part number IPS=N.A., Part number NEMS=101900493, Supplier Part Number 1=AP2127K-ADJTRG1DITR-ND
U6: "1.0 A Load Switch IC with Slew Rate Control Driver in Ultra Small Package", Manufacturer=Toshiba, Manufacturer Part Number=TCK106AG,LF, Part number IPS=00000004390, Part number NEMS=101900575, Part number Norautron=26500627, Supplier Part Number 1=TCK106AGLFTR-ND
X1: library part XTAL_SMD1612_40MHz_8pF_Kyocera, "XTAL SMD 1612, 40MHz, Cl=8pF, Total Tol: ±10ppm, -30 - 85C", Manufacturer=Kyocera, Manufacturer Part Number=CX1612DB40000D0WLLCC, Part number IPS=N.A., Part number NEMS=101600104

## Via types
v1: diameter 0.5, hole 0.25, Top Layer to Bottom Layer, tented both sides, 439 vias
v2: diameter 0.3, hole 0.1, Top Layer to Mid-Layer 1, tented both sides, 70 vias

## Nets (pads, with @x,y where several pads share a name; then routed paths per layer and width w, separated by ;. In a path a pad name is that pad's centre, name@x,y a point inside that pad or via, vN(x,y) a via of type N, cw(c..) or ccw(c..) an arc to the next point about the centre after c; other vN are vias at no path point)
ANT: C24.2 F1.6 | length 10
  Top Layer w1: 22.26,37.365 cw(c24.633,37.365) 24.633,39.738 C24.2@30.944,39.738
ANTWIFI: A1.4 R2.1
BUCKEN: P1.7 R10.1 U1.30 | length 17.5
  Top Layer w0.114: U1.30@22.66,27.095 22.66,26.518 23.094,26.084 23.094,25.792 23.16,25.726 23.16,25.527 23.411,25.276 23.411,25.108 v2(23.594,24.925)
  Top Layer w0.152: R10.1@26.571,21.694 v2@26.571,22.227
  Top Layer w0.2: P1.7@19.685,15.545 19.685,15.955 20.295,16.565 20.315,16.565 22.575,18.825 24.225,18.825 26.571,21.171 R10.1@26.571,21.694
  Mid-Layer 1 w0.2: v2(23.594,24.925) 24.369,24.925 25.394,23.9 25.394,23.383 v2(26.569,22.208)
CS: SB3.1 SB8.1 U1.36 | length 19.1
  Top Layer w0.152: U1.36@25.06,27.095 26.855,27.095 27.842,26.108 29.243,26.108 v2(33.275,26.108)
  Top Layer w0.254: SB8.1@38.735,18.727 38.735,19.02 v2(38.735,19.206) SB3.1@38.735,19.685
  Mid-Layer 1 w0.152: v2(33.275,26.108) 37.963,21.42 37.963,19.442 38.2,19.206 v2(38.735,19.206)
